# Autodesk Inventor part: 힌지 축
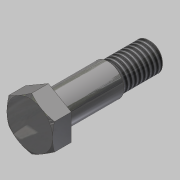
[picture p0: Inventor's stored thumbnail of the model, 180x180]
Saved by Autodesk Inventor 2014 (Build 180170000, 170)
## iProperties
Created: 2019-09
Part Number: 힌지 축
Material: 스테인리스강
Document SubType Name: Modeling
Designer: mduedu
Density: 1 g/cm^3
Appearance: 반광택
Author: mduedu
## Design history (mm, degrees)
sketch "스케치1"
  geometry: C1 r 4 at (0, 0); 1 further point
  constraints: 1 centre point, 1 coincident
  dimensions: "d0" = 8 diameter of C1
extrude "돌출1" new body sketch "스케치1" distance "d1" = 29; taper "d2" = 0 deg
sketch "스케치2"
  geometry: C1 r 4.5 at (0, 0); 1 further point
  constraints: 1 centre point, 1 coincident
  dimensions: "d3" = 9 diameter of C1
extrude "돌출2" join sketch "스케치2" distance "d4" = 17.5; taper "d5" = 0 deg
sketch "스케치3"
  geometry: L1 (0, 7.506)-(6.5, 3.753); L2 (6.5, 3.753)-(6.5, -3.753); L3 (6.5, -3.753)-(0, -7.506); L4 (0, -7.506)-(-6.5, -3.753); L5 (-6.5, -3.753)-(-6.5, 3.753); L6 (-6.5, 3.753)-(0, 7.506); C1 r 6.5 at (0, 0); 2 further points
  constraints: 12 end point, 2 coincident, 1 centre point, 1 tangent, 1 vertical alignment, 13 other
  dimensions: "d6" = 6.5 radius of C1
extrude "돌출3" join sketch "스케치3" distance "d8" = 5.3; taper "d9" = 0 deg
sketch "스케치4"
  geometry: L1 (-4, 11.5)-(-4.5, 11.5) reference; L2 (-4.5, 11.5)-(-4.5, 29) reference; L3 (-4.5, 29)-(-7.506, 29) reference; L4 (-7.506, 29)-(-7.506, 34.3) reference; L5 (-7.506, 34.3)-(7.506, 34.3) reference; L6 (7.506, 34.3)-(7.506, 29) reference; L7 (7.506, 29)-(4.5, 29) reference; L8 (4.5, 29)-(4.5, 11.5) reference; L9 (4.5, 11.5)-(4, 11.5) reference; L10 (4, 11.5)-(4, 0) reference; L11 (4, 0)-(-4, 0) reference; L12 (-4, 0)-(-4, 11.5) reference; L13 (0, 0)-(0, 34.3); L14 (7.506, 34.3)-(7.506, 33.746); L15 (6.506, 34.3)-(7.506, 33.746); L16 (7.506, 34.3)-(6.506, 34.3); L17 (4.5, 29)-(4, 29); L18 (4, 29)-(4, 28.5); L19 (4, 28.5)-(4.5, 28.5); L20 (4.5, 28.5)-(4.5, 29)
  constraints: 16 end point, 2 parallel, 2 perpendicular, 2 point on line, 1 horizontal, 1 midpoint
  dimensions: "d10" = 1 distance of L5.end L15.start; "d11" = 29 deg angle of L15 L5; "d12" = 0.5 distance of L19.end L7.end; "d13" = 0.5 distance of L18.end L19.end
revolve "회전1" sketch "스케치4" stored, may be unused: angle "d14" = 90 deg
feature "스레드1" dims "d15" = 10, "d16" = 0
chamfer "모따기1" distance "d17" = 0.5; stored, may be unused: second distance "d18" = 2, angle "d19" = 45 deg
chamfer "모따기2" distance "d20" = 0.5; stored, may be unused: second distance "d21" = 2, angle "d22" = 45 deg
node "솔리드1"
node "절단 모서리 투영1"
